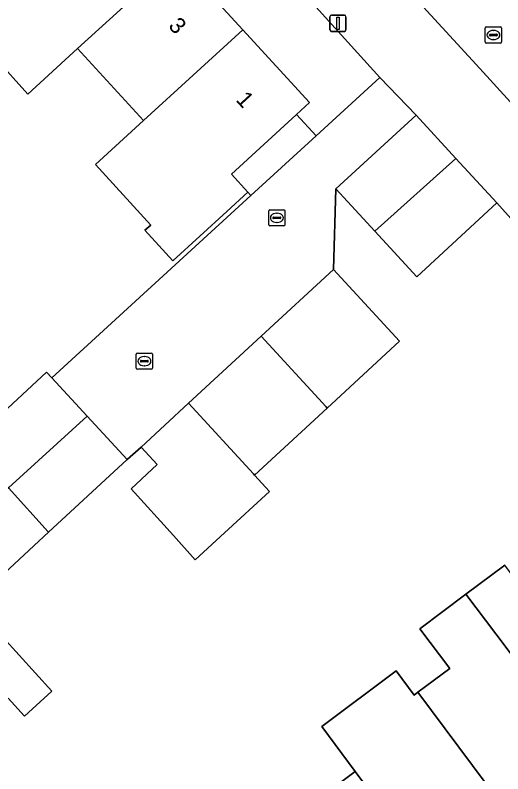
# Model space of a CAD drawing. Extents: x 158472 to 159562, y 388525 to 389606.
# Drawn here: x 159054.85 to 159084.85, y 388890.47 to 388937.09 of the extents above; entities that cross this region are included whole.
import ezdxf

# ---------------------------------------------------------------- set-up
doc = ezdxf.new("R2010")
doc.units = 0
for name, color, linetype in [('IMGEO_Erf', 7, 'Continuous'), ('IMGEO_Hek', 7, 'Continuous'), ('IMGEO_Kolk', 7, 'Continuous'), ('IMGEO_Lichtmast', 7, 'Continuous'), ('IMGEO_Pand', 7, 'Continuous'), ('IMGEO_Pand_nummerreeks', 7, 'Continuous'), ('IMGEO_Rijbaan_lokaal_open', 7, 'Continuous'), ('IMGEO_Voetpad_open', 7, 'Continuous')]:
    doc.layers.add(name, color=color, linetype=linetype)

msp = doc.modelspace()

# ---------------------------------------------------------------- linework, layer by layer
at = {"layer": 'IMGEO_Erf'}
for points in [[(159052.637, 388953.909), (159054.98, 388951.351), (159056.697, 388949.475), (159058.38, 388947.638), (159060.754, 388945.045), (159063.058, 388942.529), (159064.805, 388940.621), (159066.462, 388938.812), (159068.864, 388936.188), (159072.95, 388931.727), (159072.153, 388930.997), (159073.36, 388929.677), (159077.292, 388933.272), (159072.177, 388938.914), (159072.727, 388940.876), (159070.954, 388942.926), (159067.55, 388946.643), (159062.838, 388951.72), (159059.438, 388955.433), (159054.726, 388960.554)], [(159051.996, 388910.732), (159056.776, 388915.153), (159057.097, 388914.806), (159069.354, 388926.014), (159069.163, 388926.223), (159067.862, 388925.032), (159064.543, 388921.993), (159062.821, 388923.873), (159063.187, 388924.192), (159059.789, 388927.924), (159062.747, 388930.618), (159058.689, 388935.049), (159055.629, 388932.247), (159053.618, 388934.443)], [(159086.918, 388922.834), (159084.485, 388925.551), (159079.556, 388921.014), (159076.965, 388923.829), (159074.582, 388926.417), (159074.429, 388921.462), (159078.495, 388917.051), (159074.044, 388912.948), (159069.568, 388908.823), (159070.489, 388907.822), (159067.728, 388905.28), (159065.927, 388903.625), (159064.591, 388905.105), (159061.985, 388907.991), (159063.59, 388909.47), (159062.593, 388910.552), (159061.734, 388909.793), (159056.892, 388905.314), (159052.102, 388900.883)], [(159073.709, 388893.373), (159078.284, 388896.796), (159079.398, 388895.308), (159079.623, 388895.476), (159081.58, 388896.941), (159079.742, 388899.383), (159082.584, 388901.51), (159084.964, 388903.291)], [(159053.054, 388899.965), (159057.103, 388895.546), (159055.425, 388894.008), (159054.409, 388895.117)], [(159051.756, 388872.635), (159056.585, 388876.249), (159061.389, 388879.844), (159059.006, 388883.042), (159063.811, 388886.624), (159066.188, 388883.436), (159070.98, 388887.022), (159075.773, 388890.609), (159073.709, 388893.373)]]:
    msp.add_lwpolyline(points, dxfattribs=at)
at = {"layer": 'IMGEO_Hek'}
msp.add_lwpolyline([(159074.429, 388921.462), (159074.582, 388926.417)], dxfattribs=at)
at = {"layer": 'IMGEO_Kolk'}
for p, q in [((159083.846, 388936.375), (159084.698, 388936.375)), ((159083.771, 388935.449), (159083.771, 388936.301)), ((159084.03, 388935.869), (159084.03, 388935.881)), ((159084.073, 388935.918), (159084.471, 388935.918)), ((159084.259, 388936.155), (159084.284, 388936.155)), ((159084.514, 388935.881), (159084.514, 388935.869)), ((159084.772, 388936.301), (159084.772, 388935.449)), ((159084.468, 388935.832), (159084.07, 388935.832)), ((159084.282, 388935.595), (159084.257, 388935.595)), ((159084.698, 388935.375), (159083.846, 388935.375)), ((159070.522, 388925.139), (159071.374, 388925.139)), ((159070.447, 388924.213), (159070.447, 388925.065)), ((159070.749, 388924.682), (159071.147, 388924.682)), ((159070.935, 388924.919), (159070.96, 388924.919)), ((159071.448, 388925.065), (159071.448, 388924.213)), ((159070.706, 388924.633), (159070.706, 388924.645)), ((159071.144, 388924.596), (159070.746, 388924.596)), ((159070.958, 388924.359), (159070.933, 388924.359)), ((159071.19, 388924.645), (159071.19, 388924.633)), ((159071.374, 388924.139), (159070.522, 388924.139)), ((159062.37, 388916.33), (159063.222, 388916.33)), ((159062.295, 388915.404), (159062.295, 388916.256)), ((159062.554, 388915.824), (159062.554, 388915.836)), ((159062.597, 388915.873), (159062.995, 388915.873)), ((159062.783, 388916.11), (159062.808, 388916.11)), ((159063.038, 388915.836), (159063.038, 388915.824)), ((159063.296, 388916.256), (159063.296, 388915.404)), ((159062.992, 388915.787), (159062.594, 388915.787)), ((159062.806, 388915.55), (159062.781, 388915.55)), ((159063.222, 388915.33), (159062.37, 388915.33))]:
    msp.add_line(p, q, dxfattribs=at)
for points in [[(159083.846, 388936.375), (159084.698, 388936.375)], [(159083.771, 388935.449), (159083.771, 388936.301)], [(159084.772, 388936.301), (159084.772, 388935.449)], [(159084.698, 388935.375), (159083.846, 388935.375)], [(159070.522, 388925.139), (159071.374, 388925.139)], [(159070.447, 388924.213), (159070.447, 388925.065)], [(159071.448, 388925.065), (159071.448, 388924.213)], [(159071.374, 388924.139), (159070.522, 388924.139)], [(159062.37, 388916.33), (159063.222, 388916.33)], [(159062.295, 388915.404), (159062.295, 388916.256)], [(159063.296, 388916.256), (159063.296, 388915.404)], [(159063.222, 388915.33), (159062.37, 388915.33)]]:
    msp.add_lwpolyline(points, dxfattribs=at)
for centre, radius, start, end in [((159083.848, 388936.299), 0.0765, 91.552, 178.448), ((159083.848, 388936.299), 0.0765, 91.552, 178.448), ((159084.696, 388936.299), 0.0765, 1.552, 88.448), ((159084.696, 388936.299), 0.0765, 1.552, 88.448), ((159084.07, 388935.878), 0.0403, 85.8775, 175.7526), ((159084.067, 388935.868), 0.0366, 178.938, 274.7102), ((159084.471, 388935.875), 0.043, 264.8664, 352.4533), ((159084.475, 388935.88), 0.0386, 1.7309, 96.639), ((159083.848, 388935.451), 0.0765, 181.552, 268.448), ((159083.848, 388935.451), 0.0765, 181.552, 268.448), ((159084.696, 388935.451), 0.0765, 271.552, 358.448), ((159084.696, 388935.451), 0.0765, 271.552, 358.448), ((159070.524, 388925.063), 0.0765, 91.552, 178.448), ((159070.524, 388925.063), 0.0765, 91.552, 178.448), ((159071.372, 388925.063), 0.0765, 1.552, 88.448), ((159071.372, 388925.063), 0.0765, 1.552, 88.448), ((159070.746, 388924.642), 0.0403, 85.8775, 175.7526), ((159071.151, 388924.644), 0.0386, 1.7309, 96.639), ((159070.524, 388924.215), 0.0765, 181.552, 268.448), ((159070.524, 388924.215), 0.0765, 181.552, 268.448), ((159070.743, 388924.632), 0.0366, 178.938, 274.7102), ((159071.147, 388924.639), 0.043, 264.8664, 352.4533), ((159071.372, 388924.215), 0.0765, 271.552, 358.448), ((159071.372, 388924.215), 0.0765, 271.552, 358.448), ((159062.372, 388916.254), 0.0765, 91.552, 178.448), ((159062.372, 388916.254), 0.0765, 91.552, 178.448), ((159063.22, 388916.254), 0.0765, 1.552, 88.448), ((159063.22, 388916.254), 0.0765, 1.552, 88.448), ((159062.594, 388915.833), 0.0403, 85.8775, 175.7526), ((159062.591, 388915.823), 0.0366, 178.938, 274.7102), ((159062.995, 388915.83), 0.043, 264.8664, 352.4533), ((159062.999, 388915.835), 0.0386, 1.7309, 96.639), ((159062.372, 388915.406), 0.0765, 181.552, 268.448), ((159062.372, 388915.406), 0.0765, 181.552, 268.448), ((159063.22, 388915.406), 0.0765, 271.552, 358.448), ((159063.22, 388915.406), 0.0765, 271.552, 358.448)]:
    msp.add_arc(centre, radius, start, end, dxfattribs=at)
for centre, major_axis, ratio, start_param, end_param in [((159084.258, 388935.875), (-0.387, 0.002), 0.722429, 4.712389, 7.853982), ((159084.283, 388935.875), (-0.39, 0.002), 0.717154, 1.570796, 4.712389), ((159070.934, 388924.639), (-0.387, 0.002), 0.722429, 4.712389, 7.853982), ((159070.959, 388924.639), (-0.39, 0.002), 0.717154, 1.570796, 4.712389), ((159062.782, 388915.83), (-0.387, 0.002), 0.722429, 4.712389, 7.853982), ((159062.807, 388915.83), (-0.39, 0.002), 0.717154, 1.570796, 4.712389)]:
    msp.add_ellipse(centre, major_axis=major_axis, ratio=ratio, start_param=start_param, end_param=end_param, dxfattribs=at)
at = {"layer": 'IMGEO_Lichtmast'}
for p, q in [((159074.21, 388936.195), (159074.21, 388936.995)), ((159074.21, 388936.995), (159074.21, 388936.195)), ((159074.31, 388937.095), (159075.1, 388937.095)), ((159075.1, 388937.095), (159074.31, 388937.095)), ((159075.2, 388936.995), (159075.2, 388936.195)), ((159075.2, 388936.195), (159075.2, 388936.995)), ((159075.1, 388936.095), (159074.31, 388936.095)), ((159074.31, 388936.095), (159075.1, 388936.095))]:
    msp.add_line(p, q, dxfattribs=at)
msp.add_lwpolyline([(159074.63, 388936.97), (159074.78, 388936.97), (159074.78, 388936.22), (159074.63, 388936.22), (159074.63, 388936.97)], dxfattribs=at)
for centre, start, end in [((159074.31, 388936.995), 90, 180), ((159074.31, 388936.995), 90, 180), ((159075.1, 388936.995), 0, 90), ((159075.1, 388936.995), 360, 90), ((159074.31, 388936.195), 180, 270), ((159074.31, 388936.195), 180, 270), ((159075.1, 388936.195), 270, 0), ((159075.1, 388936.195), 270, 0)]:
    msp.add_arc(centre, 0.1, start, end, dxfattribs=at)
at = {"layer": 'IMGEO_Pand'}
for points in [[(159064.805, 388940.621), (159063.058, 388942.529), (159060.754, 388945.045), (159054.841, 388939.653), (159054.641, 388939.47), (159051.575, 388936.674), (159053.618, 388934.443), (159055.629, 388932.247), (159058.689, 388935.049)], [(159058.689, 388935.049), (159062.747, 388930.618), (159068.864, 388936.188), (159066.462, 388938.812), (159064.805, 388940.621)], [(159072.125, 388930.971), (159072.153, 388930.997), (159072.95, 388931.727), (159068.864, 388936.188), (159062.747, 388930.618), (159059.789, 388927.924), (159063.187, 388924.192), (159062.821, 388923.873), (159064.543, 388921.993), (159067.862, 388925.032), (159069.163, 388926.223), (159068.149, 388927.33)], [(159073.36, 388929.677), (159072.153, 388930.997), (159072.125, 388930.971), (159068.149, 388927.33), (159069.163, 388926.223), (159069.354, 388926.014)], [(159081.967, 388928.286), (159079.511, 388930.955), (159074.582, 388926.417), (159076.965, 388923.829)], [(159081.967, 388928.286), (159076.965, 388923.829), (159079.556, 388921.014), (159084.485, 388925.551)], [(159069.992, 388917.372), (159073.99, 388913.02), (159074.044, 388912.948), (159078.495, 388917.051), (159074.429, 388921.462)], [(159069.568, 388908.823), (159074.044, 388912.948), (159073.99, 388913.02), (159069.992, 388917.372), (159065.512, 388913.243), (159069.51, 388908.9)], [(159059.274, 388912.453), (159057.097, 388914.806), (159056.776, 388915.153), (159051.996, 388910.732), (159054.43, 388908.05)], [(159069.568, 388908.823), (159069.51, 388908.9), (159065.512, 388913.243), (159062.593, 388910.552), (159063.59, 388909.47), (159061.985, 388907.991), (159064.591, 388905.105), (159065.927, 388903.625), (159067.728, 388905.28), (159070.489, 388907.822)], [(159059.274, 388912.453), (159054.43, 388908.05), (159056.88, 388905.33), (159056.892, 388905.314), (159061.734, 388909.793)], [(159049.561, 388903.63), (159052.102, 388900.883), (159056.892, 388905.314), (159056.88, 388905.33), (159054.43, 388908.05)], [(159089.222, 388902.661), (159089.009, 388902.501), (159088.632, 388902.219), (159086.795, 388900.844), (159084.964, 388903.291), (159082.584, 388901.51), (159084.422, 388899.068), (159089.429, 388892.434), (159094.191, 388895.998)], [(159082.584, 388901.51), (159079.742, 388899.383), (159081.58, 388896.941), (159079.623, 388895.476), (159085.501, 388887.603), (159090.34, 388891.218), (159089.429, 388892.434), (159084.422, 388899.068)], [(159047.598, 388897.093), (159051.66, 388892.69), (159051.69, 388892.651), (159054.409, 388895.117), (159055.425, 388894.008), (159057.103, 388895.546), (159053.054, 388899.965), (159051.375, 388898.427), (159050.287, 388899.534)], [(159081.773, 388882.577), (159083.925, 388884.183), (159082.85, 388885.622), (159085.501, 388887.603), (159079.623, 388895.476), (159079.398, 388895.308), (159078.284, 388896.796), (159073.709, 388893.373), (159075.773, 388890.609)], [(159081.773, 388882.577), (159075.773, 388890.609), (159070.98, 388887.022), (159075.904, 388880.423), (159080.449, 388883.824), (159081.521, 388882.389)]]:
    msp.add_lwpolyline(points, close=True, dxfattribs=at)
at = {"layer": 'IMGEO_Rijbaan_lokaal_open'}
for points in [[(159077.068, 388946.614), (159078.421, 388947.93), (159070.323, 388956.636), (159068.016, 388954.544), (159067.989, 388954.52), (159066.034, 388952.748), (159083.426, 388933.811), (159089.944, 388926.697), (159093.717, 388922.579), (159096.429, 388919.62), (159105.116, 388910.008), (159108.037, 388912.648), (159101.529, 388919.848), (159102.952, 388921.161), (159101.944, 388922.249), (159100.534, 388920.949), (159092.522, 388929.727)], [(159074.429, 388921.462), (159074.582, 388926.417), (159079.511, 388930.955), (159077.292, 388933.272), (159073.36, 388929.677), (159069.354, 388926.014), (159057.097, 388914.806), (159059.274, 388912.453), (159061.734, 388909.793), (159062.593, 388910.552), (159065.512, 388913.243), (159069.992, 388917.372)]]:
    msp.add_lwpolyline(points, close=True, dxfattribs=at)
at = {"layer": 'IMGEO_Voetpad_open'}
for points in [[(159083.426, 388933.811), (159066.034, 388952.748), (159067.989, 388954.52), (159068.016, 388954.544), (159067.162, 388955.486), (159058.942, 388964.389), (159062.236, 388967.43), (159062.836, 388967.979), (159062.048, 388968.84), (159062.363, 388969.113), (159060.302, 388971.495)], [(159072.177, 388938.914), (159077.292, 388933.272), (159079.511, 388930.955), (159081.967, 388928.286), (159084.485, 388925.551), (159086.918, 388922.834), (159089.367, 388922.726), (159097.472, 388913.899), (159102.46, 388908.501), (159102.901, 388908.014), (159105.034, 388905.658), (159105.828, 388907.279), (159103.858, 388908.871), (159095.056, 388918.414), (159096.429, 388919.62), (159093.717, 388922.579), (159092.361, 388921.336), (159088.994, 388925.01), (159088.587, 388925.454), (159089.944, 388926.697), (159083.426, 388933.811)]]:
    msp.add_lwpolyline(points, dxfattribs=at)

# ---------------------------------------------------------------- texts
at = {"layer": 'IMGEO_Pand_nummerreeks'}
for s, rotation, p in [('3', 312.4817, (159064.226, 388936.397)), ('1', 312.4789, (159068.383, 388931.858))]:
    msp.add_text(s, height=1, rotation=rotation, dxfattribs=at).set_placement(p)

doc.saveas('drawing.dxf')
